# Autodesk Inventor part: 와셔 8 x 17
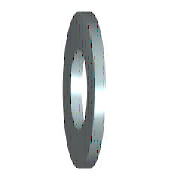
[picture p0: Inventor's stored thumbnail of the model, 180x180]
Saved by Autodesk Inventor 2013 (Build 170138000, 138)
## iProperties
IsCustomPart: 1
Created: 2012-02
Part Number: 와셔 8 x 17
Material: 강철, 연강
Description: 평면 와셔
Document SubType Name: Modeling
Standard: KS B 1326
Designer: mduedu
Standards Organization: KS
Language: ko-KR
Size Designation: 8x17
Categories: <MemberInstance><Categories><Category DisplayName="조임쇠" InternalName="e4da775c-781d-43d5-af7c-5136215cf5a6" Mnemonic="FSTN"><Category DisplayName="와셔" InternalN
Density: 7.86 g/cm^3
Mass: 2.15757 g
Surface Area: 4.70799 cm^2
Volume: 0.2745 cm^3
Author: mduedu
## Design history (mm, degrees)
sketch "스케치"
  geometry: C1 r 8.5 at (0, 0); C2 r 4.2 at (0, 0); 1 further point
  constraints: 2 centre point, 2 coincident
  dimensions: "d0" = 8.4 diameter of C2 (= SD1); "d1" = 17 diameter of C1 (= SD2)
extrude "본체" new body sketch "스케치" distance "d2" = 1.6 (= SD); taper "d3" = 0 deg
workaxis "Work Axis1"
workplane "Work Plane1"
body "Solid1"
other parameters: "SD1" = 8.4 [user parameter; used in 1 equation term], "SD2" = 17 [user parameter; used in 1 equation term], "SD" = 1.6 [user parameter; used in 1 equation term], "d4" = 0, "d5" = 0, "d6" = 0, "d7" = 0, "NND" = 8 [user parameter]
